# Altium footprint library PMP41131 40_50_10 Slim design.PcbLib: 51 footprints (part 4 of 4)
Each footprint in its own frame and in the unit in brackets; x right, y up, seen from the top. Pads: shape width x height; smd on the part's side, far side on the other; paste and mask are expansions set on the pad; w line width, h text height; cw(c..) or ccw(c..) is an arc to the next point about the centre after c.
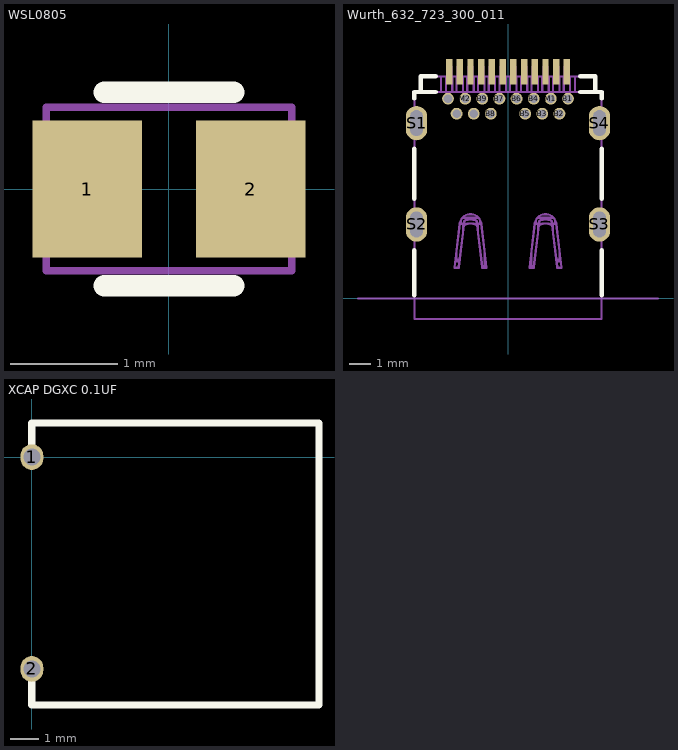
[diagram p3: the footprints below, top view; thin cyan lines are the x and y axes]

## WSL0805 [mm] "Vishay"
height 0.59
pads (2):
  rect 1.02x1.27 smd: 1(-0.76,0) 2(0.76,0)
Top Overlay:
  lines w0.2: -0.6,-0.9 0.6,-0.9 ; -0.6,0.9 0.6,0.9
Mechanical 5:
  lines w0.07: -1.142,-0.762 -1.142,0.762 1.142,0.762 1.142,-0.762 -1.142,-0.762
  text ".Designator" at -1,-0.3 h0.55
3D body: height 0.59, standoff 0, extent -1.141,-0.761 -0.601,0.761
3D body: height 0.59, standoff 0, extent -0.599,-0.761 0.599,0.761
3D body: height 0.59, standoff 0, extent 0.601,-0.761 1.141,0.761

## Wurth_632_723_300_011 [mm] "Connector, Receptacle, USB Type C, R/A"
height 3.11
pads (30):
  rect 0.3x1.2 smd: A1(-2.75,10.58) A2(-2.25,10.58) A3(-1.75,10.58) A4(-1.25,10.58) A5(-0.75,10.58) A6(-0.25,10.58) A7(0.25,10.58) A8(0.75,10.58) A9(1.25,10.58) A10(1.75,10.58) A11(2.25,10.58) A12(2.75,10.58)
  round 0.55 hole 0.4: B1(2.8,9.32) B2(2.4,8.62) B3(1.6,8.62) B4(1.2,9.32) B5(0.8,8.62) B6(0.4,9.32) B7(-0.4,9.32) B8(-0.8,8.62) B9(-1.2,9.32) B10(-1.6,8.62) B11(-2.4,8.62) B12(-2.8,9.32) M1(2,9.32) M2(-2,9.32)
  rrect100% 1x1.6 hole 0.6 slot 1.2 at 90 deg: S1(-4.27,8.18) S2(-4.27,3.45) S3(4.27,3.45) S4(4.27,8.18)
Top Overlay:
  lines w0.2: -4.37,0.15 -4.37,2.25 ; -4.37,4.65 -4.37,6.98 ; -4.37,9.325 -4.37,9.631 -3.37,9.631 ; -4.07,9.631 -4.07,10.361 -3.375,10.361 ; 3.37,9.631 4.37,9.631 4.37,9.325 ; 3.375,10.361 4.07,10.361 4.07,9.631 ; 4.37,0.15 4.37,2.25 ; 4.37,4.65 4.37,6.98
Mechanical 1:
  lines w0.1: -7,0 7,0
Mechanical 5:
  drawing of 6386 lines, arcs and shapes, not listed
  text ".Designator" at -1.95,5.6 h1.02
3D body "632723100011.stp": height 3.07, standoff -1.78, extent -4.37,-0.965 4.37,10.829

## XCAP DGXC 0.1UF [mm]
pads (2):
  oval 0.8x0.9 hole 0.6: 1(0,0) 2(0,-7.4)
Top Overlay:
  lines w0.254: 0,-7.461 0,-8.661 10.033,-8.661 10.033,1.194 ; 0,0 0,1.194 10,1.194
